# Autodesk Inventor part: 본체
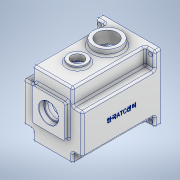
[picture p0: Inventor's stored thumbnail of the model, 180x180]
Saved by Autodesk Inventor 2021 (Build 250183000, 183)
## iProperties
Created: 2022-08
Part Number: 본체
Material: 알루미늄 6061
Document SubType Name: Modeling
Designer: Owner
Density: 2.7 g/cm^3
Appearance: 알루미늄 - 평지
Mass: 1403.37 g
Surface Area: 1172.14 cm^2
Volume: 519.766 cm^3
Author: Owner
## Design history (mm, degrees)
sketch "스케치1"
  geometry: L1 (-49, -55)-(49, -55); L2 (49, -55)-(49, 55); L3 (49, 55)-(-49, 55); L4 (-49, 55)-(-49, -55); L5 (-49, -55)-(49, 55); L6 (49, -55)-(-49, 55); 1 further point
  constraints: 12 end point, 2 midpoint, 2 parallel, 1 horizontal, 1 perpendicular
  dimensions: "d0" = 98 distance of L2.end L3.end; "d1" = 110 distance of L3.end L1.start
extrude "돌출1" new body sketch "스케치1" distance "d2" = 130; taper "d3" = 0 deg
sketch "스케치2"
  geometry: L1 (49, 55)-(-49, 55) reference; L2 (-49, 55)-(-33, 55); L3 (-33, 55)-(-33, 28); L4 (-33, 28)-(-49, 28); L5 (-49, 28)-(-49, 55); 2 further points
  constraints: 8 end point, 2 parallel, 1 horizontal, 1 perpendicular
  dimensions: "d4" = 27 distance of L4.end L1.end; "d5" = 16 distance of L3.end L4.end
extrude "돌출2" cut sketch "스케치2" distance "d6" = 120; taper "d7" = 0 deg
sketch "스케치3"
  geometry: L1 (-49, -55)-(49, -55) reference; L2 (-49, -55)-(-33, -55); L3 (-33, -55)-(-33, -38); L4 (-33, -38)-(-49, -38); L5 (-49, -38)-(-49, -55); 2 further points
  constraints: 8 end point, 2 parallel, 1 horizontal, 1 perpendicular
  dimensions: "d8" = 17 distance of L4.end L1.start; "d9" = 16 distance of L3.end L4.end
extrude "돌출3" cut sketch "스케치3" distance "d10" = 120; taper "d11" = 0 deg
sketch "스케치4"
  geometry: L1 (98, 0)-(0, 0) reference; C1 r 15 at (49, -89); 2 further points
  constraints: 1 centre point, 1 midpoint, 1 vertical alignment
  dimensions: "d12" = 30 diameter of C1; "d13" = 89 distance of point (49, 0) C1.centre
extrude "돌출4" join sketch "스케치4" distance "d14" = 5; taper "d15" = 0 deg
sketch "스케치5"
  geometry: L1 (98, 0)-(0, 0) reference; C1 r 22.5 at (49, -40); 2 further points
  constraints: 1 centre point, 1 midpoint, 1 vertical alignment
  dimensions: "d16" = 40 distance of point (49, 0) C1.centre; "d17" = 45 diameter of C1
extrude "돌출5" join sketch "스케치5" distance "d18" = 10; taper "d19" = 0 deg
sketch "스케치6"
  geometry: L1 (-27, 33)-(27, 33); L2 (27, 33)-(27, -21); L3 (27, -21)-(-27, -21); L4 (-27, -21)-(-27, 33); L5 (-27, 33)-(27, -21); L6 (27, 33)-(-27, -21); L7 (-33, -55)-(33, -55) reference; 3 further points
  constraints: 12 end point, 3 midpoint, 2 parallel, 1 horizontal, 1 perpendicular, 1 vertical alignment
  dimensions: "d20" = 54 distance of L1.start L1.end; "d21" = 54 distance of L1.end L2.end; "d39" = 61 distance from line of L7 point (0, 6)
sketch "스케치7"
  geometry: L1 (49, -55)-(-49, -55) reference; L2 (-23, 45)-(23, 45); L3 (-23, 45)-(-23, 30.143); L4 (0, -79)-(0, 89) reference; L5 (23, 45)-(23, 30.143); L6 (-26, 31.729)-(-26, 48); L7 (-26, 48)-(26, 48); L8 (26, 48)-(26, 31.729); A1 r 42 centre (0, -5) between (-23, 30.143) and (23, 30.143); A2 r 45 centre (0, -5) between (-26, 31.729) and (26, 31.729); 1 further point
  constraints: 12 end point, 4 point on circle, 2 centre point, 2 symmetric about line, 1 horizontal, 1 vertical, 1 vertical alignment, 3 other
  dimensions: "d22" = 50 distance from line of L1 A1.centre; "d23" = 84 diameter of A1; "d24" = 50 distance from line of A1.centre L2; "d25" = 23 distance from line of point (0, 0) L3; "d26" = 3 radial gap between concentric circles of A1 A2
extrude "돌출6" cut sketch "스케치7" distance "d27" = 9; taper "d28" = 0 deg
sketch "스케치8"
  geometry: L1 (23, 30.143)-(23, 45) reference; L2 (23, 45)-(-23, 45) reference; L3 (-23, 45)-(-23, 30.143) reference; L4 (-82.202, -5)-(83.378, -5); L5 (0, -71.333)-(0, 75.392); L6 (-35.777, -1)-(-41.809, -1); L7 (-35.777, -9)-(-41.809, -9); L8 (35.777, -1)-(41.809, -1); L9 (35.777, -9)-(41.809, -9); A1 r 42 centre (0, -5) between (-23, 30.143) and (23, 30.143) reference; A2 r 42 centre (0, -5) between (-23, 30.143) and (23, 30.143) reference; A3 r 36 centre (0, -5) between (-36, -5) and (-35.777, -1); A4 r 4 centre (-36, -5) between (-36, -9) and (-36, -1); A5 r 4 centre (36, -5) between (36, -1) and (36, -9); 9 further points
  constraints: 12 end point, 9 point on circle, 9 symmetric about line, 7 point on line, 3 centre point, 2 horizontal, 2 tangent, 1 coincident, 1 parallel, 1 vertical, 1 other
  dimensions: "d29" = 72 diameter of A3; "d30" = 8 diameter of A4
extrude "돌출7" cut sketch "스케치8" distance "d31" = 114; taper "d32" = 0 deg
sketch "스케치9"
  geometry: L1 (-68.808, -5)-(75.827, -5); L2 (-68.808, 6)-(75.827, 6); L3 (0, -92.071)-(0, 86.583); L4 (-36, -1)-(-41.809, -1) reference; L5 (-41.809, -9)-(-36, -9) reference; L6 (36, -9)-(41.809, -9) reference; L7 (41.809, -1)-(36, -1) reference; L8 (23, 45)-(23, 30.143) reference; L9 (-23, 45)-(23, 45) reference; L10 (-23, 30.143)-(-23, 45) reference; A1 r 42 centre (0, -5) between (-41.809, -9) and (41.809, -9) reference; A2 r 21 centre (0, 6) between (8.978, -12.984) and (-8.978, -12.984); A3 r 15 centre (0, -25) between (-8.978, -12.984) and (8.978, -12.984); A4 r 42 centre (0, -5) between (-23, 30.143) and (-41.809, -1) reference; A5 r 4 centre (-36, -5) between (-36, -9) and (-36, -1) reference; A6 r 42 centre (0, -5) between (-41.809, -9) and (41.809, -9) reference; A7 r 4 centre (36, -5) between (36, -1) and (36, -9) reference; A8 r 42 centre (0, -5) between (41.809, -1) and (23, 30.143) reference; 3 further points
  constraints: 6 end point, 5 point on line, 4 point on circle, 2 centre point, 1 horizontal, 1 parallel, 1 vertical
  dimensions: "d33" = 11 distance between parallel lines of L1 L2; "d34" = 42 diameter of A2; "d35" = 30 diameter of A3; "d36" = 20 distance of A1.centre A3.centre
extrude "돌출8" cut sketch "스케치9" distance "d37" = 7; taper "d38" = 0 deg
extrude "돌출9" join sketch "스케치6" distance "d40" = 7; taper "d41" = 0 deg
sketch "스케치10"
  geometry: L1 (-33, -55)-(33, -55) reference; 2 further points
  constraints: 1 vertical alignment
  dimensions: "d42" = 61 distance from line of L1 point (0, 6)
hole "구멍1" sketch "스케치10" at (0, 6) diameter "d43" = 28; stored, may be unused: countersink angle "d47" = 90 deg, drill point angle "d49" = 0 deg; dims "d44" = 8, "d45" = 32, "d46" = 8.3, "d48" = 40
sketch "스케치11"
  geometry: C1 r 14 at (0, 6) reference; C2 r 17.5 at (0, 6); 1 further point
  constraints: 1 centre point, 1 coincident
  dimensions: "d50" = 35 diameter of C2
extrude "돌출10" cut sketch "스케치11" distance "d51" = 10; taper "d52" = 0 deg
sketch "스케치12"
  geometry: A1 r 15 centre (0, -25) between (-8.978, -12.984) and (8.978, -12.984) reference; 2 further points
  constraints: 1 coincident
hole "구멍2" sketch "스케치12" at (0, -25) diameter "d53" = 19; stored, may be unused: countersink angle "d57" = 90 deg, drill point angle "d59" = 0 deg; dims "d54" = 8, "d55" = 22, "d56" = 7, "d58" = 10
sketch "스케치13"
  geometry: C1 r 15 at (23, 80) reference; 2 further points
  constraints: 1 coincident
hole "구멍3" sketch "스케치13" at (23, 80) diameter "d60" = 20; stored, may be unused: countersink angle "d64" = 90 deg, drill point angle "d66" = 0 deg; dims "d61" = 8, "d62" = 30, "d63" = 5, "d65" = 10
sketch "스케치14"
  geometry: C1 r 22.5 at (0, 0) reference; 2 further points
  constraints: 1 coincident
hole "구멍4" sketch "스케치14" at (0, 0) diameter "d67" = 33.376; stored, may be unused: countersink angle "d71" = 90 deg, drill point angle "d73" = 0 deg; dims "d68" = 70, "d69" = 19.05, "d70" = 4.775, "d72" = 10
sketch "스케치15"
  geometry: A1 r 4 centre (-36, -5) between (-36, -9) and (-36, -1) reference; 2 further points
  constraints: 1 coincident
hole "구멍5" sketch "스케치15" at (-36, -5) diameter "d74" = 3.242; stored, may be unused: countersink angle "d78" = 90 deg, drill point angle "d80" = 118 deg; dims "d75" = 16, "d76" = 19.05, "d77" = 4.775, "d79" = 18
fillet "모깎기1" dims "d81" = 0.3
fillet "모깎기2" dims "d82" = 0.3
fillet "모깎기3" dims "d83" = 0.3
fillet "모깎기5" dims "d85" = 3
fillet "모깎기6" dims "d86" = 3
fillet "모깎기7" dims "d87" = 3
fillet "모깎기8" dims "d88" = 3
fillet "모깎기9" dims "d89" = 3
fillet "모깎기10" dims "d90" = 3
fillet "모깎기11" dims "d91" = 3
fillet "모깎기12" dims "d92" = 3
fillet "모깎기13" dims "d93" = 3
fillet "모깎기14" dims "d94" = 3
fillet "모깎기15" dims "d95" = 3
fillet "모깎기17" dims "d97" = 6
fillet "모깎기18" dims "d98" = 3
fillet "모깎기19" dims "d99" = 3
chamfer "모따기1" distance "d100" = 0.8; stored, may be unused: second distance "d101" = 2, angle "d102" = 30 deg
chamfer "모따기2" distance "d103" = 1; stored, may be unused: second distance "d104" = 2, angle "d105" = 30 deg
chamfer "모따기3" distance "d106" = 1; stored, may be unused: second distance "d107" = 2, angle "d108" = 30 deg
sketch "스케치16"
  geometry: L1 (-130, 104)-(-130, 83) reference; L2 (-13, 107)-(-127, 107) reference; 2 further points
  constraints: 1 other
  dimensions: "d113" = 65 distance from line of L1 point (-65, 47); "d114" = 60 distance from line of L2 point (-65, 47)
feature "엠보싱1" sketch "스케치16" dims "d115" = 0.5, "d116" = 0
sketch "스케치17"
  geometry: L1 (41.809, -1)-(38.367, -1) reference; L2 (38.367, -9)-(41.809, -9) reference; L3 (-41.809, -9)-(-38.367, -9) reference; L4 (-38.367, -1)-(-41.809, -1) reference; L5 (-23, 42)-(-23, 33.249) reference; L6 (20, 45)-(-20, 45) reference; L7 (23, 33.249)-(23, 42) reference; L8 (-26, 48)-(26, 48) reference; L9 (-26, 31.729)-(-26, 48) reference; L10 (26, 48)-(26, 31.729) reference; L11 (-36, -1)-(-41.809, -1) reference; L12 (-41.809, -9)-(-36, -9) reference; L13 (36, -9)-(41.809, -9) reference; L14 (41.809, -1)-(36, -1) reference; A1 r 45 centre (0, -5) between (-26, 31.729) and (26, 31.729) reference; A2 r 6 centre (29, 33.249) between (23, 33.249) and (25.375, 28.468) reference; A3 r 42 centre (0, -5) between (41.318, 2.538) and (25.375, 28.468) reference; A4 r 3 centre (38.367, 2) between (38.367, -1) and (41.318, 2.538) reference; A5 r 42 centre (0, -5) between (41.809, -9) and (41.809, -1) reference; A6 r 3 centre (38.367, -12) between (41.318, -12.538) and (38.367, -9) reference; A7 r 42 centre (0, -5) between (-41.318, -12.538) and (41.318, -12.538) reference; A8 r 3 centre (-38.367, -12) between (-38.367, -9) and (-41.318, -12.538) reference; A9 r 42 centre (0, -5) between (-41.809, -1) and (-41.809, -9) reference; A10 r 3 centre (-38.367, 2) between (-41.318, 2.538) and (-38.367, -1) reference; A11 r 42 centre (0, -5) between (-25.375, 28.468) and (-41.318, 2.538) reference; A12 r 6 centre (-29, 33.249) between (-25.375, 28.468) and (-23, 33.249) reference; A13 r 3 centre (-20, 42) between (-20, 45) and (-23, 42) reference; A14 r 3 centre (20, 42) between (23, 42) and (20, 45) reference; A15 r 45 centre (0, -5) between (-26, 31.729) and (26, 31.729) reference; A16 r 4 centre (-36, -5) between (-36, -9) and (-36, -1) reference; A17 r 4 centre (36, -5) between (36, -1) and (36, -9) reference; 3 further points
extrude "돌출11" cut sketch "스케치17" distance "d117" = 10; taper "d118" = 0 deg
fillet "모깎기21" dims "d119" = 3
chamfer "모따기5" distance "d120" = 1; stored, may be unused: second distance "d121" = 2, angle "d122" = 30 deg
sketch "스케치18"
  geometry: L1 (-49, -52)-(-49, 52) reference; L2 (-46, 55)-(46, 55) reference; 2 further points
  dimensions: "d123" = 7 distance from line of point (-42, 48) L1; "d124" = 7 distance from line of L2 point (-42, 48)
hole "구멍6" sketch "스케치18" at (-42, 48) diameter "d125" = 7; stored, may be unused: countersink angle "d129" = 90 deg, drill point angle "d131" = 118 deg; dims "d126" = 7, "d127" = 19.05, "d128" = 4.775, "d130" = 9
node "솔리드1"
mirror "미러1"
mirror "미러2"
mirror "미러3"
mirror "미러4"
mirror "미러5"
node "투영된 루프1"
node "투영된 루프2"
node "투영된 루프3"
feature "A9D066F2-1C7D-4E18-AEED-F7BC21143FA4" dims "d43" = 28, "d44" = 8, "d45" = 32, "d46" = 8.3, "d47" = 90 deg, "d48" = 40, "d49" = 0
